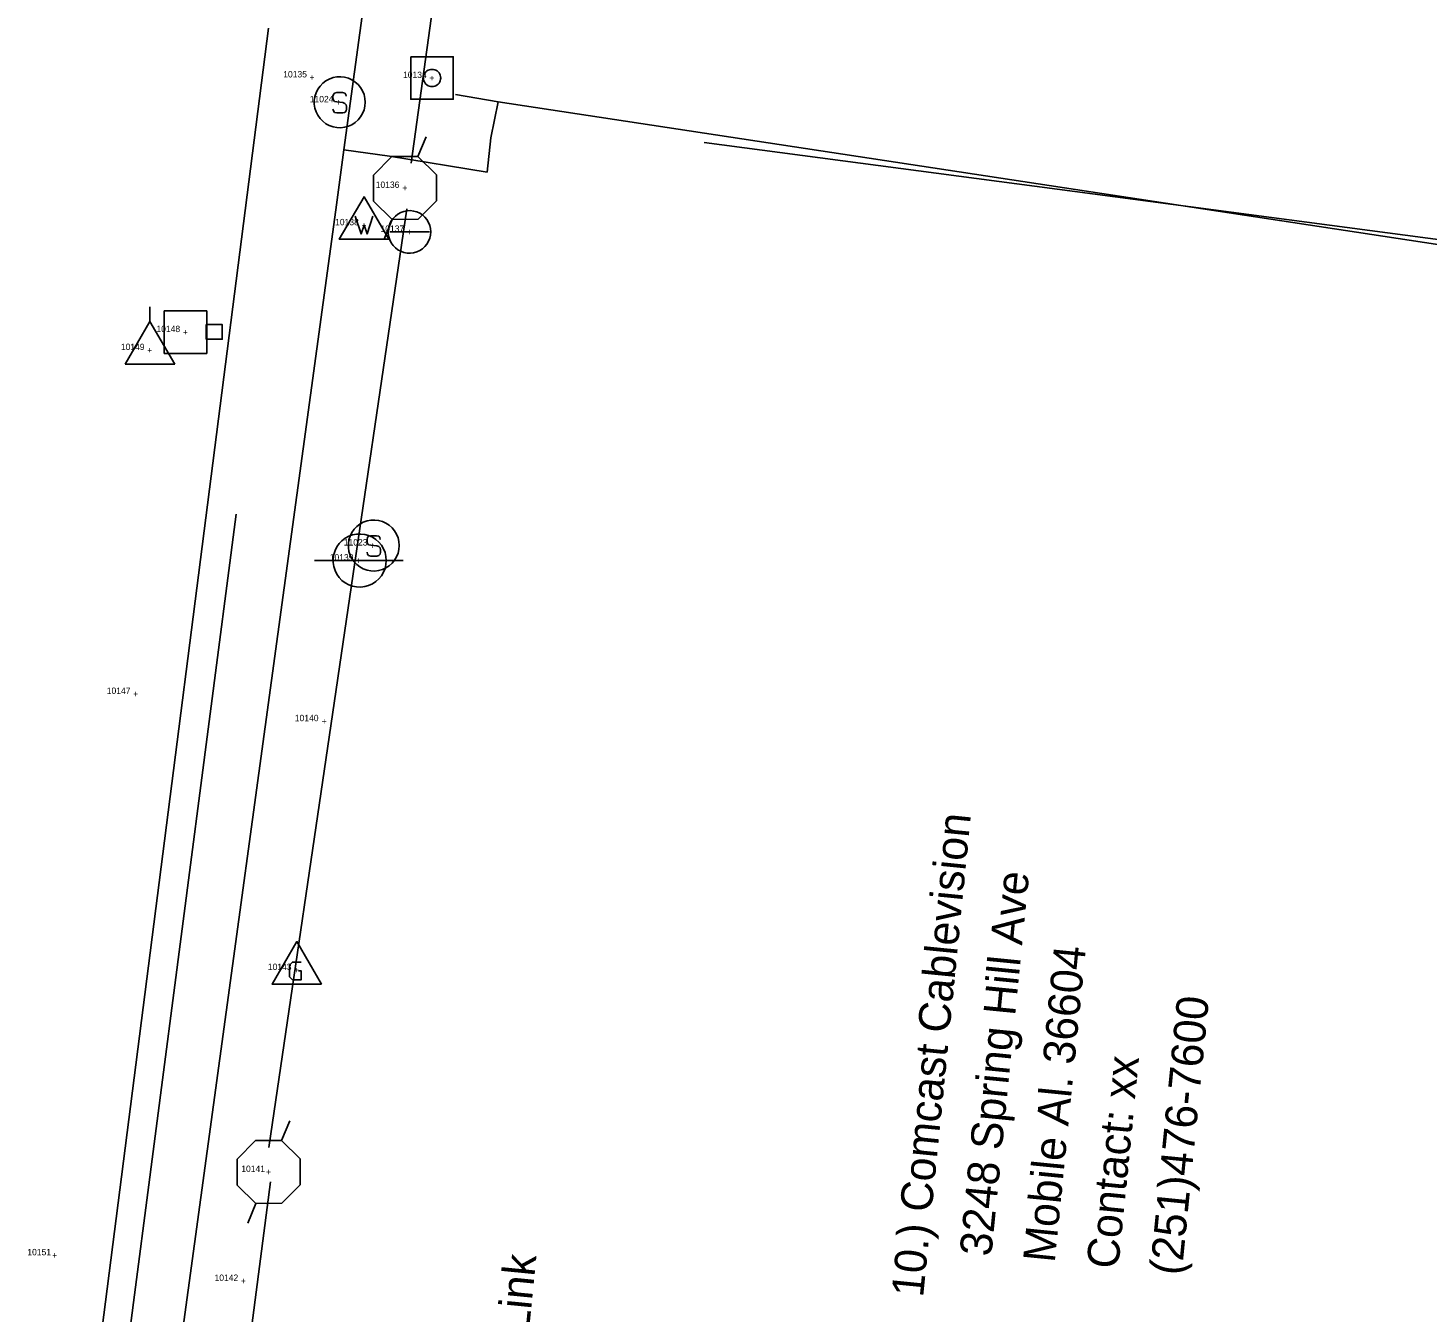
# Model space of a CAD drawing. Extents: x 1795905 to 1799611, y 243768 to 252016.
# Drawn here: x 1797772.7 to 1798102.1, y 246679.9 to 246982 of the extents above; entities that cross this region are included whole.
import ezdxf

# ---------------------------------------------------------------- set-up
doc = ezdxf.new("R2010")
doc.units = 0
for name, color, linetype in [('2', 7, 'Continuous'), ('Level 50', 7, 'Continuous'), ('LS-SURVEY POINT', 7, 'Continuous'), ('OHUT', 7, 'Continuous'), ('OHUTTXT', 7, 'Continuous'), ('UGUT', 7, 'Continuous'), ('UGUTTXT', 7, 'Continuous')]:
    doc.layers.add(name, color=color, linetype=linetype)

msp = doc.modelspace()

# ---------------------------------------------------------------- linework, layer by layer
at = {"layer": 'Level 50'}
for p, q in [((1797864.48, 246951.75), (1797866.38, 246956.37)), ((1797856.5, 246932.33), (1797858.4, 246936.95)), ((1797832.41, 246720.25), (1797834.31, 246724.87)), ((1797824.43, 246700.83), (1797826.33, 246705.45))]:
    msp.add_line(p, q, dxfattribs=at)
for points in [[(1797864.52, 246936.97), (1797858.4, 246936.95), (1797854.06, 246941.27), (1797854.04, 246947.39), (1797858.36, 246951.73), (1797864.48, 246951.75), (1797868.82, 246947.43), (1797868.84, 246941.31)], [(1797832.45, 246705.47), (1797826.33, 246705.45), (1797821.99, 246709.77), (1797821.97, 246715.89), (1797826.29, 246720.23), (1797832.41, 246720.25), (1797836.75, 246715.93), (1797836.77, 246709.81)]]:
    msp.add_lwpolyline(points, close=True, dxfattribs=at)
at = {"layer": 'OHUT'}
for p, q in [((1797801.42, 246912.9), (1797801.42, 246916.4)), ((1797795.58, 246902.9), (1797807.25, 246902.9)), ((1797840.14, 246856.69), (1797860.97, 246856.69))]:
    msp.add_line(p, q, dxfattribs=at)
msp.add_lwpolyline([(1797795.58, 246902.9), (1797801.42, 246912.9), (1797807.25, 246902.9)], dxfattribs=at)
for points in [[(1797804.78, 246915.43), (1797814.78, 246915.43), (1797814.78, 246905.43), (1797804.78, 246905.43)], [(1797814.67, 246912.21), (1797814.67, 246908.74), (1797818.43, 246908.74), (1797818.43, 246912.21)], [(1797857.02, 246856.69), (1797856.94, 246857.64), (1797856.73, 246858.58), (1797856.37, 246859.46), (1797855.88, 246860.29), (1797855.27, 246861.02), (1797854.55, 246861.66), (1797853.75, 246862.18), (1797852.88, 246862.57), (1797851.96, 246862.83), (1797851.01, 246862.93), (1797850.05, 246862.9), (1797849.11, 246862.72), (1797848.21, 246862.39), (1797847.37, 246861.94), (1797846.61, 246861.36), (1797845.94, 246860.67), (1797845.39, 246859.88), (1797844.97, 246859.03), (1797844.68, 246858.11), (1797844.53, 246857.17), (1797844.53, 246856.21), (1797844.68, 246855.27), (1797844.97, 246854.35), (1797845.39, 246853.5), (1797845.94, 246852.71), (1797846.61, 246852.02), (1797847.37, 246851.44), (1797848.21, 246850.99), (1797849.11, 246850.66), (1797850.05, 246850.48), (1797851.01, 246850.44), (1797851.96, 246850.55), (1797852.88, 246850.81), (1797853.75, 246851.2), (1797854.55, 246851.72), (1797855.27, 246852.36), (1797855.88, 246853.09), (1797856.37, 246853.92), (1797856.73, 246854.8), (1797856.94, 246855.74)]]:
    msp.add_lwpolyline(points, close=True, dxfattribs=at)
at = {"layer": 'OHUTTXT'}
for p, q in [((1797862.92, 246950.18), (1797882.04, 247088.92)), ((1797829.41, 246718.59), (1797861.86, 246939.47)), ((1797818.92, 246626.39), (1797829.78, 246710.51))]:
    msp.add_line(p, q, dxfattribs=at)
at = {"layer": 'UGUT'}
for p, q in [((1797844.49, 246965.46), (1797844.49, 246965.91)), ((1797844.62, 246965.01), (1797844.49, 246965.46)), ((1797847.25, 246966.68), (1797846.73, 246966.81)), ((1797847.5, 246966.36), (1797847.25, 246966.68)), ((1797847.63, 246965.91), (1797847.5, 246966.36)), ((1797844.49, 246962.9), (1797844.62, 246962.45)), ((1797844.88, 246964.69), (1797844.62, 246965.01)), ((1797844.62, 246962.45), (1797844.88, 246962.13)), ((1797845.39, 246964.57), (1797844.88, 246964.69)), ((1797846.8, 246964.44), (1797845.39, 246964.57)), ((1797846.8, 246964.44), (1797847.31, 246964.25)), ((1797847.63, 246963.93), (1797847.31, 246964.25)), ((1797847.31, 246962.13), (1797847.63, 246962.45)), ((1797847.69, 246963.48), (1797847.63, 246963.93)), ((1797847.63, 246962.45), (1797847.69, 246962.9)), ((1797847.69, 246962.9), (1797847.69, 246963.48)), ((1797844.88, 246962.13), (1797845.39, 246962.01)), ((1797845.39, 246962.01), (1797846.8, 246962.01)), ((1797846.8, 246962.01), (1797847.31, 246962.13)), ((1797857.83, 246934.01), (1797867.17, 246934.01)), ((1797852.5, 246861.18), (1797852.5, 246861.63)), ((1797852.63, 246860.73), (1797852.5, 246861.18)), ((1797852.88, 246860.41), (1797852.63, 246860.73)), ((1797853.39, 246860.28), (1797852.88, 246860.41)), ((1797854.8, 246860.16), (1797853.39, 246860.28)), ((1797855.25, 246862.4), (1797854.74, 246862.52)), ((1797854.8, 246860.16), (1797855.31, 246859.96)), ((1797855.51, 246862.08), (1797855.25, 246862.4)), ((1797855.63, 246861.63), (1797855.51, 246862.08)), ((1797852.5, 246858.62), (1797852.63, 246858.17)), ((1797852.63, 246858.17), (1797852.88, 246857.85)), ((1797852.88, 246857.85), (1797853.39, 246857.72)), ((1797853.39, 246857.72), (1797854.8, 246857.72)), ((1797854.8, 246857.72), (1797855.31, 246857.85)), ((1797855.63, 246859.64), (1797855.31, 246859.96)), ((1797855.31, 246857.85), (1797855.63, 246858.17)), ((1797855.7, 246859.2), (1797855.63, 246859.64)), ((1797855.63, 246858.17), (1797855.7, 246858.62)), ((1797855.7, 246858.62), (1797855.7, 246859.2))]:
    msp.add_line(p, q, dxfattribs=at)
for points in [[(1797862.8, 246975.21), (1797872.8, 246975.21), (1797872.8, 246965.21), (1797862.8, 246965.21)], [(1797867.8, 246972.25), (1797868.12, 246972.23), (1797868.43, 246972.15), (1797868.72, 246972.03), (1797869, 246971.86), (1797869.24, 246971.65), (1797869.45, 246971.41), (1797869.61, 246971.14), (1797869.74, 246970.84), (1797869.81, 246970.53), (1797869.84, 246970.21), (1797869.81, 246969.9), (1797869.74, 246969.58), (1797869.61, 246969.29), (1797869.45, 246969.02), (1797869.24, 246968.77), (1797869, 246968.57), (1797868.72, 246968.4), (1797868.43, 246968.28), (1797868.12, 246968.2), (1797867.8, 246968.18), (1797867.48, 246968.2), (1797867.17, 246968.28), (1797866.88, 246968.4), (1797866.6, 246968.57), (1797866.36, 246968.77), (1797866.15, 246969.02), (1797865.99, 246969.29), (1797865.86, 246969.58), (1797865.79, 246969.9), (1797865.76, 246970.21), (1797865.79, 246970.53), (1797865.86, 246970.84), (1797865.99, 246971.14), (1797866.15, 246971.41), (1797866.36, 246971.65), (1797866.6, 246971.86), (1797866.88, 246972.03), (1797867.17, 246972.15), (1797867.48, 246972.23)], [(1797852.09, 246964.5), (1797852.01, 246965.42), (1797851.81, 246966.31), (1797851.46, 246967.16), (1797850.99, 246967.95), (1797850.41, 246968.66), (1797849.72, 246969.27), (1797848.95, 246969.77), (1797848.11, 246970.15), (1797847.23, 246970.39), (1797846.31, 246970.5), (1797845.4, 246970.46), (1797844.5, 246970.29), (1797843.63, 246969.97), (1797842.82, 246969.54), (1797842.09, 246968.98), (1797841.46, 246968.32), (1797840.93, 246967.57), (1797840.52, 246966.74), (1797840.24, 246965.87), (1797840.1, 246964.96), (1797840.1, 246964.04), (1797840.24, 246963.13), (1797840.52, 246962.26), (1797840.93, 246961.43), (1797841.46, 246960.68), (1797842.09, 246960.02), (1797842.82, 246959.46), (1797843.63, 246959.03), (1797844.5, 246958.71), (1797845.4, 246958.54), (1797846.31, 246958.5), (1797847.23, 246958.61), (1797848.11, 246958.85), (1797848.95, 246959.23), (1797849.72, 246959.73), (1797850.41, 246960.34), (1797850.99, 246961.05), (1797851.46, 246961.84), (1797851.81, 246962.69), (1797852.01, 246963.58)], [(1797857.65, 246932.27), (1797851.82, 246942.27), (1797845.98, 246932.27)], [(1797867.5, 246934.01), (1797867.44, 246934.77), (1797867.27, 246935.52), (1797866.98, 246936.23), (1797866.59, 246936.89), (1797866.1, 246937.48), (1797865.53, 246937.99), (1797864.89, 246938.4), (1797864.19, 246938.72), (1797863.45, 246938.92), (1797862.69, 246939.01), (1797861.93, 246938.98), (1797861.17, 246938.83), (1797860.45, 246938.57), (1797859.78, 246938.21), (1797859.17, 246937.74), (1797858.64, 246937.19), (1797858.2, 246936.57), (1797857.86, 246935.88), (1797857.63, 246935.15), (1797857.51, 246934.39), (1797857.51, 246933.63), (1797857.63, 246932.87), (1797857.86, 246932.14), (1797858.2, 246931.46), (1797858.64, 246930.83), (1797859.17, 246930.28), (1797859.78, 246929.81), (1797860.45, 246929.45), (1797861.17, 246929.19), (1797861.93, 246929.04), (1797862.69, 246929.01), (1797863.45, 246929.1), (1797864.19, 246929.3), (1797864.89, 246929.62), (1797865.53, 246930.03), (1797866.1, 246930.54), (1797866.59, 246931.13), (1797866.98, 246931.79), (1797867.27, 246932.5), (1797867.44, 246933.25)], [(1797860.09, 246860.22), (1797860.02, 246861.13), (1797859.81, 246862.03), (1797859.47, 246862.88), (1797859, 246863.67), (1797858.41, 246864.38), (1797857.73, 246864.99), (1797856.96, 246865.49), (1797856.12, 246865.86), (1797855.23, 246866.11), (1797854.32, 246866.21), (1797853.4, 246866.18), (1797852.5, 246866), (1797851.63, 246865.69), (1797850.83, 246865.25), (1797850.1, 246864.7), (1797849.46, 246864.04), (1797848.93, 246863.28), (1797848.52, 246862.46), (1797848.25, 246861.58), (1797848.11, 246860.68), (1797848.11, 246859.76), (1797848.25, 246858.85), (1797848.52, 246857.98), (1797848.93, 246857.15), (1797849.46, 246856.4), (1797850.1, 246855.74), (1797850.83, 246855.18), (1797851.63, 246854.74), (1797852.5, 246854.43), (1797853.4, 246854.26), (1797854.32, 246854.22), (1797855.23, 246854.33), (1797856.12, 246854.57), (1797856.96, 246854.95), (1797857.73, 246855.45), (1797858.41, 246856.06), (1797859, 246856.77), (1797859.47, 246857.56), (1797859.81, 246858.41), (1797860.02, 246859.3)], [(1797841.83, 246757.05), (1797836, 246767.05), (1797830.17, 246757.05)]]:
    msp.add_lwpolyline(points, close=True, dxfattribs=at)
for points in [[(1797844.49, 246965.91), (1797844.62, 246966.36), (1797844.88, 246966.68)], [(1797846.73, 246966.81), (1797845.39, 246966.81), (1797844.88, 246966.68)], [(1797849.73, 246937.69), (1797851.12, 246933.52), (1797851.82, 246935.61), (1797852.51, 246933.52), (1797853.9, 246937.69)], [(1797852.5, 246861.63), (1797852.63, 246862.08), (1797852.88, 246862.4)], [(1797854.74, 246862.52), (1797853.39, 246862.52), (1797852.88, 246862.4)], [(1797836.35, 246760.13), (1797837.04, 246760.13), (1797837.04, 246758.05), (1797834.96, 246758.05), (1797834.27, 246758.74), (1797834.27, 246761.52), (1797834.96, 246762.22), (1797837.04, 246762.22)]]:
    msp.add_lwpolyline(points, dxfattribs=at)
at = {"layer": 'UGUTTXT'}
for p, q in [((1797784.86, 246634.22), (1797829.32, 246981.95)), ((1797789.02, 246616.72), (1797821.72, 246867.61))]:
    msp.add_line(p, q, dxfattribs=at)
for points in [[(1797899.65, 247338.24), (1797847.06, 246953.29)], [(1798198.39, 247319.71), (1798143, 246927.09), (1797931.84, 246955.05)], [(1797883.37, 246964.6), (1797873.33, 246966.36)], [(1797881.62, 246956.12), (1797883.37, 246964.6)], [(1798146.22, 246924.7), (1797883.37, 246964.6)], [(1797881.62, 246956.12), (1797880.76, 246948.03)], [(1797847.06, 246953.29), (1797845.14, 246939.22)], [(1797857.8, 246951.82), (1797847.06, 246953.29)], [(1797880.76, 246948.03), (1797857.8, 246951.82)], [(1797845.14, 246939.22), (1797802.74, 246628.82)]]:
    msp.add_lwpolyline(points, dxfattribs=at)

# ---------------------------------------------------------------- texts
at = {"layer": '2'}
for s, p in [('10.) Comcast Cablevision', (1797983.31, 246683.2)), ('    3248 Spring Hill Ave', (1797998.24, 246681.72)), ('    Mobile Al. 36604', (1798013.17, 246680.24)), ('    (251)476-7600', (1798043.02, 246677.29)), ('    Contact: xx', (1798028.09, 246678.76)), ('5.) Madison Rivers Communication,d/b/a CenturyLink', (1797868.96, 246456.81))]:
    msp.add_text(s, height=7.5, rotation=84.3427, dxfattribs=at).set_placement(p)
at = {"layer": 'LS-SURVEY POINT'}
for s, p in [('10135', (1797832.79, 246970.34)), ('+', (1797838.99, 246969.59)), ('10134', (1797860.97, 246970.21)), ('+', (1797867.17, 246969.46)), ('11024', (1797839.03, 246964.5)), ('+', (1797845.23, 246963.75)), ('10136', (1797854.54, 246944.35)), ('+', (1797860.82, 246943.6)), ('10138', (1797844.99, 246935.57)), ('+', (1797851.19, 246934.82)), ('10137', (1797855.67, 246934.01)), ('+', (1797861.87, 246933.26)), ('10148', (1797802.96, 246910.43)), ('+', (1797809.16, 246909.68)), ('10149', (1797794.59, 246906.2)), ('+', (1797800.79, 246905.45)), ('11023', (1797847.03, 246860.22)), ('+', (1797853.23, 246859.47)), ('10139', (1797843.73, 246856.69)), ('+', (1797849.93, 246855.94)), ('10147', (1797791.28, 246825.3)), ('+', (1797797.48, 246824.55)), ('10140', (1797835.52, 246818.89)), ('+', (1797841.84, 246818.14)), ('10143', (1797829.17, 246760.35)), ('+', (1797835.37, 246759.6)), ('10141', (1797822.92, 246712.85)), ('+', (1797828.75, 246712.1)), ('10151', (1797772.59, 246693.24)), ('+', (1797778.42, 246692.49)), ('10142', (1797816.63, 246687.21)), ('+', (1797822.83, 246686.46))]:
    msp.add_text(s, height=1.5, dxfattribs=at).set_placement(p)
at = {"layer": 'UGUT'}
msp.add_text('+', height=1, rotation=360, dxfattribs=at).set_placement((1797867.37, 246969.71))

doc.saveas('drawing.dxf')
